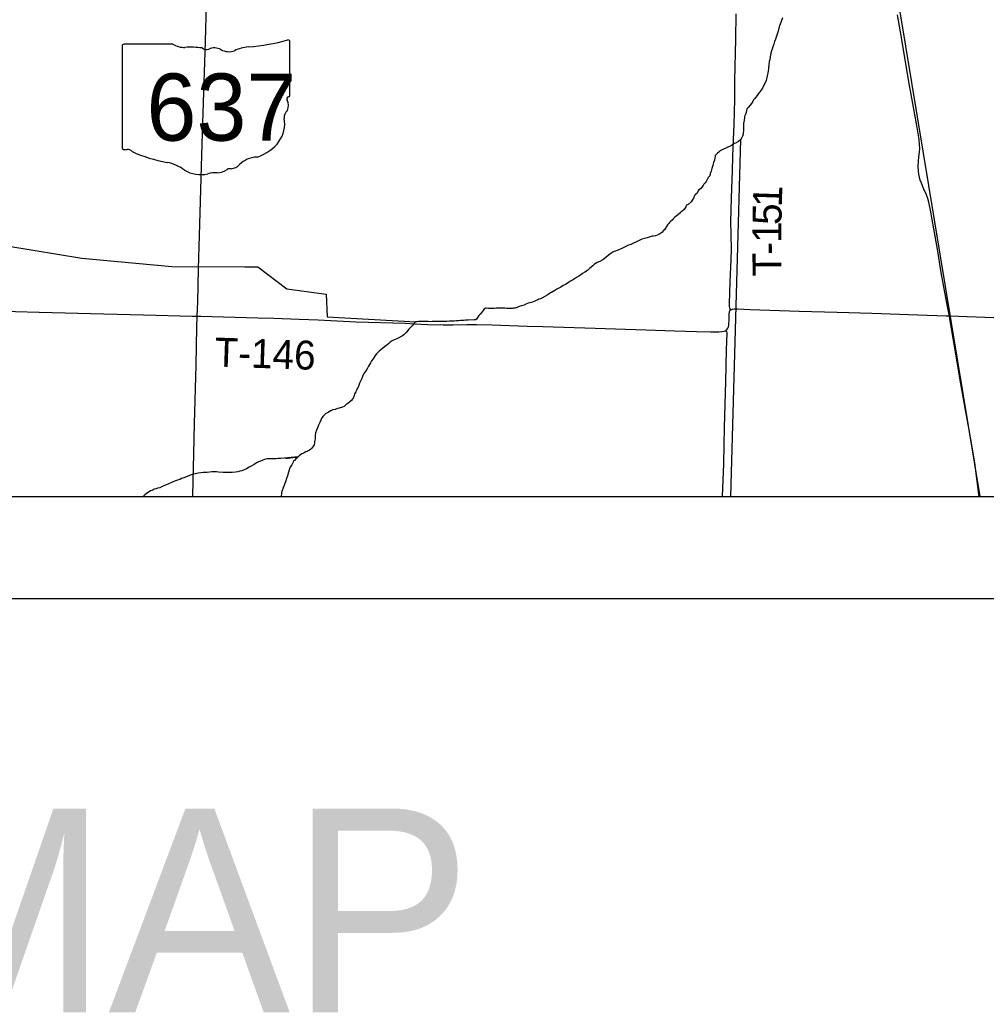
# Model space of a CAD drawing. Extents: x 2.1 to 73.9, y 4 to 26.
# Drawn here: x 45.863 to 46.811, y 17.596 to 18.573 of the extents above; entities that cross this region are included whole.
import ezdxf

# ---------------------------------------------------------------- set-up
doc = ezdxf.new("R2010")
doc.units = 0
for name, color, linetype in [('GM_X_County_Road', 7, 'Continuous'), ('GM_X_Minor_River', 7, 'Continuous'), ('GM_X_State_Location', 7, 'Continuous'), ('GM_X_State_Route', 7, 'Continuous'), ('GM_X_State_Shield', 7, 'Continuous'), ('GM_X_Township_Road', 7, 'Continuous'), ('GM_X_Township_Road_Text', 7, 'Continuous'), ('SH_Data', 7, 'Continuous'), ('SH_Text', 7, 'Continuous')]:
    doc.layers.add(name, color=color, linetype=linetype)

msp = doc.modelspace()

# ---------------------------------------------------------------- linework, layer by layer
at = {"layer": 'GM_X_County_Road'}
msp.add_lwpolyline([(45.53595, 18.29575), (45.5447, 18.29559), (45.57576, 18.29489), (45.62856, 18.29355), (45.6767, 18.29223), (45.71707, 18.29117), (45.73105, 18.29082), (45.75744, 18.29007), (45.79937, 18.28893), (45.84439, 18.28733), (45.85836, 18.28687), (45.88165, 18.28625), (45.94531, 18.28459), (45.98413, 18.28355), (46.03227, 18.28223), (46.03689, 18.28232)], dxfattribs=at)
at = {"layer": 'GM_X_Minor_River'}
msp.add_line((46.56055, 18.10511), (46.57032, 18.45562), dxfattribs=at)
for points in [[(46.60821, 19.6038), (46.59551, 19.04415), (46.60176, 19.0314), (46.61094, 18.95554), (46.6172, 18.94925), (46.66663, 18.73187), (46.7097, 18.68232), (46.805, 18.10511)], [(46.6114, 18.57523), (46.61007, 18.57144), (46.60911, 18.56878), (46.60835, 18.56726), (46.60777, 18.56498), (46.60701, 18.56213), (46.60433, 18.55435), (46.60357, 18.55188), (46.6028, 18.54922), (46.60185, 18.54656), (46.60108, 18.54448), (46.60051, 18.54258), (46.59993, 18.5403), (46.59955, 18.53897), (46.59917, 18.53688), (46.59878, 18.53384), (46.59821, 18.53232), (46.59782, 18.52871)], [(46.59782, 18.52871), (46.59763, 18.52624), (46.59744, 18.52491), (46.59724, 18.5232), (46.59686, 18.52092), (46.59648, 18.51959), (46.59628, 18.51807), (46.5959, 18.51655), (46.59552, 18.51522), (46.59514, 18.51351), (46.59418, 18.51123), (46.59304, 18.50896), (46.59189, 18.50687), (46.59037, 18.50421), (46.58884, 18.50213), (46.58751, 18.50042), (46.58636, 18.4989), (46.58522, 18.4972), (46.5837, 18.49549), (46.58274, 18.49454), (46.58179, 18.49246), (46.5795, 18.48923), (46.5776, 18.48715), (46.57626, 18.48582), (46.5755, 18.48221), (46.57454, 18.47955), (46.57416, 18.47841), (46.57397, 18.47708), (46.57377, 18.4748), (46.57339, 18.47271), (46.57301, 18.47157), (46.573, 18.46853), (46.57319, 18.46644), (46.57319, 18.46511), (46.57299, 18.46378), (46.5728, 18.46264), (46.57261, 18.46093), (46.57203, 18.45884), (46.57146, 18.45751), (46.57032, 18.45562), (46.56822, 18.45372), (46.56575, 18.4524), (46.56423, 18.45183), (46.56137, 18.44975), (46.55224, 18.44541), (46.55072, 18.44484), (46.54976, 18.44427), (46.54881, 18.44333), (46.54748, 18.44219), (46.54653, 18.44124), (46.54519, 18.44011), (46.54519, 18.43916), (46.54442, 18.43536), (46.54366, 18.43308), (46.54328, 18.43175), (46.54289, 18.43023), (46.54251, 18.42928), (46.54232, 18.42814), (46.54194, 18.42719), (46.54156, 18.42586), (46.54117, 18.42472), (46.54041, 18.42244), (46.53983, 18.42017), (46.5385, 18.41827), (46.53774, 18.41694), (46.53717, 18.4158), (46.5364, 18.41447), (46.53526, 18.41315), (46.53412, 18.41182), (46.53335, 18.41068), (46.53221, 18.40878), (46.53069, 18.40727), (46.52935, 18.40632), (46.52859, 18.40518), (46.52745, 18.4031), (46.52573, 18.4012), (46.52478, 18.40063), (46.52383, 18.39797), (46.52154, 18.39437), (46.51868, 18.39172), (46.51697, 18.39115), (46.51658, 18.38944), (46.51468, 18.38698), (46.51258, 18.38508), (46.51125, 18.38433), (46.51011, 18.383), (46.50859, 18.38167), (46.50706, 18.38035), (46.50535, 18.37902), (46.50402, 18.37789), (46.50287, 18.37637), (46.50135, 18.37523), (46.5004, 18.37428), (46.49964, 18.37315), (46.49849, 18.37182), (46.49735, 18.3703), (46.49659, 18.36878), (46.49544, 18.36708), (46.49449, 18.36632), (46.49297, 18.36423), (46.48992, 18.36234)], [(46.48992, 18.36234), (46.48669, 18.36121), (46.48478, 18.36065), (46.48345, 18.36065), (46.4806, 18.35971), (46.47832, 18.35914), (46.4747, 18.3582), (46.47337, 18.35783), (46.46937, 18.35594), (46.46728, 18.355), (46.465, 18.35386), (46.46252, 18.35273), (46.46024, 18.35197), (46.45872, 18.35122), (46.45739, 18.35065), (46.45567, 18.34971), (46.45358, 18.34876), (46.4513, 18.34763), (46.44901, 18.34669), (46.44749, 18.34612), (46.44597, 18.34574), (46.44483, 18.34499), (46.44292, 18.34366), (46.44045, 18.34196), (46.43778, 18.33988), (46.43493, 18.3376), (46.43188, 18.3359), (46.42941, 18.33477), (46.4277, 18.33382), (46.42655, 18.33288), (46.42503, 18.33174), (46.42237, 18.32947), (46.41989, 18.32719), (46.41723, 18.32549), (46.41494, 18.32398), (46.41304, 18.32265), (46.41133, 18.32152), (46.40923, 18.32019), (46.40714, 18.31887), (46.40523, 18.31773), (46.40333, 18.3166), (46.40124, 18.31527), (46.39914, 18.31357), (46.3961, 18.31225), (46.39381, 18.31073), (46.39172, 18.3096), (46.38982, 18.30865), (46.38791, 18.30752), (46.3862, 18.30638), (46.38449, 18.30563), (46.38354, 18.30506), (46.3822, 18.30411), (46.3803, 18.30279), (46.37802, 18.30146), (46.37516, 18.29976), (46.37364, 18.29939), (46.37231, 18.29882), (46.37117, 18.29825), (46.3666, 18.29637), (46.36508, 18.2958), (46.36318, 18.29524), (46.36165, 18.29486), (46.35994, 18.2943), (46.35766, 18.29316), (46.35499, 18.29241), (46.3529, 18.29165), (46.351, 18.2909), (46.34891, 18.29014), (46.34739, 18.28996), (46.34624, 18.28977), (46.3451, 18.28978), (46.34396, 18.28978), (46.34244, 18.28978), (46.34073, 18.28979), (46.33864, 18.28998), (46.33598, 18.29018), (46.33446, 18.29019), (46.33332, 18.29), (46.33198, 18.29), (46.33027, 18.29001), (46.32818, 18.28982), (46.32647, 18.28964), (46.32514, 18.28964), (46.324, 18.28965), (46.32267, 18.28984), (46.32077, 18.29023), (46.31982, 18.29023), (46.31848, 18.28947), (46.31753, 18.28795), (46.3162, 18.28606), (46.31467, 18.28416), (46.31315, 18.28284), (46.31201, 18.28094), (46.31105, 18.27942), (46.30991, 18.27866), (46.30858, 18.27867), (46.30287, 18.2783), (46.30154, 18.27831), (46.30021, 18.27831), (46.29869, 18.27812), (46.29698, 18.27794)], [(45.43344, 18.29095), (45.84789, 18.28073), (45.85181, 18.35086), (45.92366, 18.33925), (46.01206, 18.33102), (46.08355, 18.33082), (46.09648, 18.33078), (46.12496, 18.30903), (46.16355, 18.30379), (46.16427, 18.28155), (46.25153, 18.27655)], [(46.29698, 18.27794), (46.29527, 18.27795), (46.29337, 18.27776), (46.29128, 18.27758), (46.28899, 18.27739), (46.28652, 18.27721), (46.28443, 18.27722), (46.28196, 18.27703), (46.28006, 18.27704), (46.27834, 18.27704), (46.27663, 18.27705), (46.27492, 18.27705), (46.27321, 18.27706), (46.27131, 18.27687), (46.26941, 18.27688), (46.26751, 18.27688), (46.2656, 18.2767), (46.26351, 18.2769), (46.26142, 18.2769), (46.25933, 18.27691), (46.25781, 18.27691), (46.25648, 18.27711), (46.2542, 18.27692), (46.25287, 18.27673), (46.25153, 18.27655), (46.2502, 18.2756), (46.24811, 18.27295), (46.2462, 18.27105), (46.24449, 18.26954), (46.24334, 18.26783), (46.24182, 18.26631), (46.24087, 18.26518), (46.23973, 18.26385), (46.2382, 18.2629), (46.23421, 18.26063), (46.23287, 18.25988), (46.23116, 18.25931), (46.22964, 18.25875), (46.22812, 18.25799), (46.2264, 18.25666), (46.22488, 18.25534), (46.22298, 18.25382), (46.22069, 18.25212), (46.21879, 18.2506), (46.21707, 18.24928), (46.21555, 18.24795), (46.21422, 18.24662), (46.21269, 18.24511), (46.21155, 18.24359), (46.21041, 18.24207), (46.20945, 18.24018), (46.20793, 18.23847), (46.20698, 18.23657), (46.20602, 18.23467), (46.20488, 18.23316), (46.20392, 18.23126), (46.20259, 18.22898), (46.20145, 18.22727), (46.20049, 18.22595), (46.19973, 18.22462), (46.19897, 18.22291), (46.19801, 18.22025), (46.19668, 18.21778), (46.1961, 18.21646), (46.19553, 18.21456), (46.19477, 18.21247), (46.194, 18.21133), (46.19343, 18.21019), (46.19305, 18.20924), (46.19248, 18.2081), (46.19191, 18.20696), (46.19133, 18.20583), (46.19057, 18.20317), (46.18942, 18.20089), (46.18847, 18.19975), (46.18676, 18.19805), (46.18466, 18.19634), (46.18276, 18.19502), (46.18104, 18.19369), (46.17933, 18.19293), (46.1761, 18.19199), (46.17439, 18.19162), (46.1721, 18.19067), (46.16982, 18.19011), (46.16811, 18.18936), (46.16621, 18.18841), (46.16468, 18.18746), (46.16316, 18.18652), (46.16221, 18.18576), (46.16049, 18.18405), (46.15916, 18.18254), (46.15821, 18.18026), (46.15706, 18.17798), (46.15592, 18.17532), (46.15496, 18.17267), (46.15382, 18.1702), (46.15305, 18.16773), (46.15267, 18.16507), (46.15266, 18.16355), (46.15247, 18.16184), (46.15228, 18.16051)], [(46.15228, 18.16051), (46.15208, 18.1588), (46.15189, 18.15785), (46.15151, 18.15595), (46.15094, 18.15481), (46.14999, 18.15367), (46.14922, 18.15253), (46.14827, 18.15159), (46.14713, 18.15064), (46.1456, 18.14988), (46.14465, 18.14951), (46.14332, 18.14894), (46.14199, 18.14799), (46.14047, 18.14743), (46.13952, 18.14705), (46.13818, 18.1461), (46.13685, 18.14516), (46.1359, 18.14421), (46.13495, 18.14307), (46.1338, 18.14212), (46.13228, 18.14061), (46.13133, 18.14023), (46.13095, 18.1389), (46.12961, 18.13624), (46.12828, 18.13454), (46.12732, 18.13226), (46.12656, 18.12922), (46.1256, 18.12561), (46.12464, 18.12276), (46.1235, 18.11953), (46.12197, 18.11536), (46.12102, 18.11308), (46.12044, 18.11156), (46.12006, 18.11061), (46.11968, 18.10833), (46.11933, 18.10511)], [(46.12335, 18.14253), (46.1359, 18.14421), (46.11897, 18.14236), (46.11631, 18.14236), (46.11422, 18.14218), (46.11251, 18.142), (46.11023, 18.142), (46.10776, 18.14201), (46.10509, 18.14202), (46.10281, 18.14145), (46.10129, 18.14089), (46.09901, 18.13994), (46.09691, 18.13938), (46.09501, 18.13824), (46.09292, 18.13673), (46.09044, 18.13541), (46.08797, 18.13389), (46.0853, 18.13238), (46.08302, 18.13143), (46.08074, 18.13049), (46.07864, 18.12993), (46.07674, 18.12955), (46.07446, 18.12918), (46.07123, 18.12881), (46.06895, 18.12881), (46.06723, 18.12863), (46.06533, 18.12863), (46.064, 18.12883), (46.06248, 18.12883), (46.05773, 18.12923), (46.05564, 18.12942), (46.05355, 18.12943), (46.05107, 18.12924), (46.04879, 18.12906), (46.0467, 18.12888), (46.0448, 18.12888), (46.04271, 18.1287), (46.04042, 18.12832), (46.03795, 18.12795), (46.0351, 18.12758), (46.03206, 18.12683), (46.02939, 18.12588), (46.02692, 18.12494), (46.02464, 18.12381), (46.02159, 18.12287), (46.01969, 18.12192), (46.0176, 18.12117), (46.01569, 18.1206), (46.01398, 18.12004), (46.0117, 18.11909), (46.00865, 18.11758), (46.00561, 18.11626), (46.00257, 18.11494), (46.00009, 18.1138), (45.99781, 18.11324), (45.99648, 18.11286), (45.99476, 18.1123), (45.99362, 18.11173), (45.99229, 18.11116), (45.99115, 18.1106), (45.98963, 18.10984), (45.9881, 18.1087), (45.98677, 18.10776), (45.98544, 18.10681), (45.98373, 18.1053), (45.98357, 18.10511)]]:
    msp.add_lwpolyline(points, dxfattribs=at)
at = {"layer": 'GM_X_State_Route'}
msp.add_lwpolyline([(46.03241, 18.10511), (46.03288, 18.12058), (46.03346, 18.147), (46.0342, 18.17652), (46.03569, 18.234), (46.03658, 18.2713), (46.03689, 18.28232), (46.03732, 18.29615), (46.03818, 18.32878), (46.03909, 18.3614), (46.04179, 18.45151), (46.0431, 18.4919), (46.04462, 18.54161), (46.04526, 18.56336), (46.04675, 18.61619), (46.04787, 18.65347), (46.04856, 18.67833), (46.04965, 18.7116)], dxfattribs=at)
at = {"layer": 'GM_X_State_Shield'}
for p, q in [((45.96312, 18.54755), (45.96312, 18.44749)), ((46.013, 18.54927), (45.96474, 18.54927)), ((46.12791, 18.49941), (46.12791, 18.55175)), ((46.12789, 18.49942), (46.12791, 18.49941))]:
    msp.add_line(p, q, dxfattribs=at)
for centre, major_axis, start_param, end_param in [((45.96501, 18.54776), (0.00191, 0), 1.712693, 3.28349), ((46.02449, 18.56089), (0.01852, 0), 4.042523, 4.731795), ((46.03063, 18.4931), (0.06648, 0), 1.404758, 1.657858), ((46.04573, 18.54828), (0.00534, 0), 3.836095, 5.185415), ((46.05357, 18.53672), (0.01111, 0), 0.950623, 2.079405), ((46.0915, 18.51871), (0.03516, 0), 1.699011, 2.107814), ((46.06921, 18.68569), (0.17476, 0), 4.814394, 5.042369), ((46.12608, 18.55197), (0.00183, 0), 6.141152, 7.989035), ((46.0679, 18.55258), (0.01336, 0), 4.081561, 5.145723), ((46.12749, 18.49557), (0.00284, 0), 1.883978, 3.671073), ((46.12595, 18.49921), (0.00196, 0), 5.05454, 6.418171), ((46.10943, 18.48895), (0.01704, 0), 5.934695, 6.695948), ((46.13448, 18.4775), (0.0124, 0), 2.387724, 3.262537), ((46.079, 18.47085), (0.04371, 0), 5.101752, 6.440018), ((45.96502, 18.44727), (0.00193, 0), 3.00124, 4.508301), ((45.96532, 18.45751), (0.0147, 0), 4.665946, 4.897461), ((45.96832, 18.44172), (0.0053, 0), 0.519207, 1.627899), ((46.03524, 18.53162), (0.1262, 0), 4.195997, 4.488961), ((46.09743, 18.4194), (0.02394, 0), 1.647645, 2.488434), ((45.99761, 18.40254), (0.03949, 0), 0.823519, 1.323587), ((46.0671, 18.43779), (0.01412, 0), 4.937069, 5.64225), ((46.04032, 18.44122), (0.02506, 0), 4.026481, 4.996735), ((46.05479, 18.40663), (0.02059, 0), 1.495662, 1.94098), ((46.05663, 18.43373), (0.01335, 0), 4.691044, 5.507374), ((46.0687, 18.42404), (0.00376, 0), 1.147584, 2.315152)]:
    msp.add_ellipse(centre, major_axis=major_axis, ratio=0.8, start_param=start_param, end_param=end_param, dxfattribs=at)
at = {"layer": 'GM_X_Township_Road'}
for points in [[(46.56013, 18.28838), (46.55961, 18.29038), (46.55944, 18.29163), (46.55931, 18.29306), (46.55932, 18.29434), (46.55971, 18.30522), (46.56002, 18.3161), (46.56088, 18.33787), (46.5611, 18.3472), (46.56088, 18.36276), (46.56073, 18.3752), (46.5613, 18.39853), (46.56221, 18.42496), (46.56256, 18.43896), (46.56318, 18.45606), (46.56372, 18.47005), (46.56449, 18.49493), (46.56454, 18.50427), (46.56464, 18.5136), (46.56544, 18.55404), (46.56584, 18.57893)], [(46.77506, 18.28251), (46.77349, 18.29012), (46.76925, 18.31276), (46.76703, 18.325), (46.76343, 18.34804), (46.75981, 18.36791), (46.75657, 18.38629), (46.75536, 18.39239), (46.75419, 18.39689), (46.75267, 18.4013), (46.75018, 18.40699), (46.74766, 18.41268), (46.74657, 18.4156), (46.7457, 18.41857), (46.7451, 18.42162), (46.74471, 18.4247), (46.74451, 18.42936), (46.74471, 18.43402), (46.74526, 18.43865), (46.74584, 18.44327), (46.74597, 18.44638), (46.74581, 18.45103), (46.74531, 18.45567), (46.7431, 18.46949), (46.73911, 18.49088), (46.73532, 18.51231), (46.73206, 18.53225), (46.72699, 18.56134), (46.72418, 18.57821)], [(46.03689, 18.28232), (46.04054, 18.28239), (46.09649, 18.28061), (46.11203, 18.28019), (46.13689, 18.27925), (46.15554, 18.27854), (46.19282, 18.27681), (46.24099, 18.27522), (46.25031, 18.2748), (46.26273, 18.2741), (46.27827, 18.27364), (46.2876, 18.27361), (46.30158, 18.27404), (46.31091, 18.27405), (46.32646, 18.27361), (46.36064, 18.27243), (46.37619, 18.27196), (46.42748, 18.2705), (46.4772, 18.26866), (46.50518, 18.26784), (46.52694, 18.26719), (46.54093, 18.26684), (46.5487, 18.26691), (46.55181, 18.26708), (46.55414, 18.26743), (46.55526, 18.26778), (46.55617, 18.26835)], [(46.55617, 18.26835), (46.55694, 18.26941), (46.55759, 18.27046), (46.55822, 18.27191), (46.55858, 18.27345), (46.55875, 18.27503), (46.55886, 18.27821), (46.55888, 18.28301), (46.55898, 18.28459), (46.55921, 18.28615), (46.55938, 18.28696), (46.55963, 18.2876), (46.56013, 18.28838)], [(46.56013, 18.28838), (46.56068, 18.28869), (46.56145, 18.28893), (46.56238, 18.2891), (46.56391, 18.28927), (46.56701, 18.28932), (46.57944, 18.28894), (46.6276, 18.28722), (46.64003, 18.28677), (46.66489, 18.28622), (46.69907, 18.28518), (46.74412, 18.28358), (46.77208, 18.28261), (46.77506, 18.28251)], [(46.77506, 18.28251), (46.81868, 18.28107), (46.85441, 18.27992), (46.87927, 18.2792), (46.91967, 18.27816), (46.94297, 18.27745), (46.98026, 18.27628), (47.05794, 18.27402), (47.09212, 18.27301), (47.11387, 18.27237), (47.14028, 18.27161), (47.20398, 18.2696), (47.21329, 18.26923), (47.2305, 18.26877), (47.23547, 18.2687), (47.24427, 18.26855), (47.24582, 18.26855), (47.24814, 18.26854)], [(46.80436, 18.10511), (46.80399, 18.1075), (46.79994, 18.13833), (46.79751, 18.15368), (46.79467, 18.17054), (46.7906, 18.19192), (46.78576, 18.21948), (46.77979, 18.25473), (46.77728, 18.27008), (46.77603, 18.27774), (46.77506, 18.28251)], [(46.55256, 18.10511), (46.55357, 18.13724), (46.55402, 18.15588), (46.55444, 18.17297), (46.55554, 18.21801), (46.55638, 18.24908), (46.5569, 18.2656), (46.55684, 18.26613), (46.55676, 18.26667), (46.55617, 18.26835)]]:
    msp.add_lwpolyline(points, dxfattribs=at)
at = {"layer": 'SH_Data'}
for p, q in [((41.95853, 18.10511), (48.75853, 18.10511)), ((41.85853, 18.00511), (48.85853, 18.00511))]:
    msp.add_line(p, q, dxfattribs=at)

# ---------------------------------------------------------------- texts
at = {"layer": 'GM_X_State_Location'}
for s in ['s', 'r']:
    msp.add_text(s, height=0.0000947, dxfattribs=at).set_placement((46.04366, 18.49087))
msp.add_text('637', height=0.0000947, rotation=0.00001, dxfattribs=at).set_placement((46.01023, 18.48398))
at = {"layer": 'GM_X_State_Shield'}
msp.add_text('637', height=0.065918, dxfattribs=at).set_placement((45.98705, 18.45455))
at = {"layer": 'GM_X_Township_Road_Text'}
for s, height, rotation, p in [('1', 0.02841, 88.08199, (46.61054, 18.389)), ('5', 0.02841, 89.03717, (46.61025, 18.37163)), ('1', 0.02841, 89.76582, (46.61018, 18.35422)), ('-', 0.02841, 90.23809, (46.61023, 18.34262)), ('T', 0.02841, 90.40072, (46.61037, 18.32139)), ('T-146', 0.028409, 358.03439, (46.05344, 18.23289))]:
    msp.add_text(s, height=height, rotation=rotation, dxfattribs=at).set_placement(p)
at = {"layer": 'SH_Text'}
msp.add_text('LOCATION MAP', height=0.2, dxfattribs=at).set_placement((44.28547, 17.59886))

doc.saveas('drawing.dxf')
